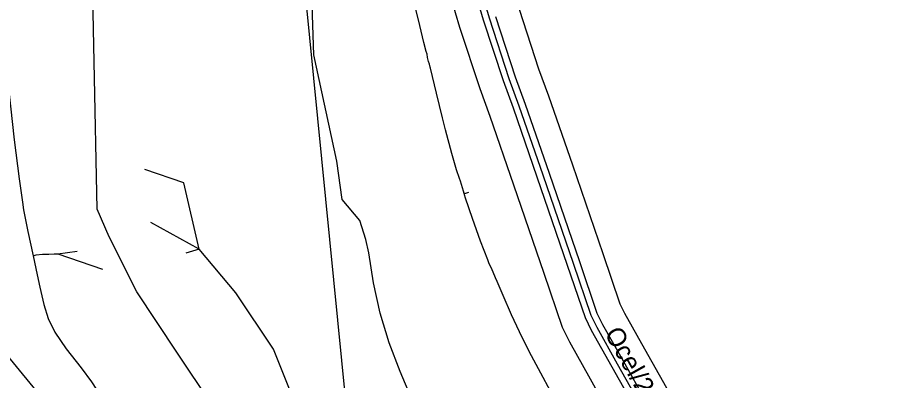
# Model space of a CAD drawing. Extents: x -555222 to -543220, y -1067119 to -1030889.
# Drawn here: x -550360 to -549789, y -1045094 to -1044860 of the extents above; entities that cross this region are included whole.
import ezdxf

# ---------------------------------------------------------------- set-up
doc = ezdxf.new("R2010")
doc.units = 0
for name, color, linetype in [('07_ELEKTRO', 7, 'Continuous'), ('07_KANALIZACE', 7, 'Continuous'), ('07_OCH_P A POPISY TI', 7, 'Continuous'), ('07_PLYNOVOD', 7, 'Continuous'), ('07_SDĚLOVACÍ', 7, 'Continuous')]:
    doc.layers.add(name, color=color, linetype=linetype)

msp = doc.modelspace()

# ---------------------------------------------------------------- linework, layer by layer
at = {"layer": '07_ELEKTRO'}
msp.add_lwpolyline([(-550336.58, -1045114.42), (-550410.66, -1045024.35)], dxfattribs=at)
at = {"layer": '07_KANALIZACE'}
msp.add_lwpolyline([(-550217.13, -1045615.96), (-550259.48, -1045440.34), (-550269.12, -1045408.84), (-550268.16, -1045382.39), (-550263.88, -1045356.4), (-550243.71, -1045306.39), (-550215.78, -1045262), (-550208.66, -1045250.35), (-550203.47, -1045219.62), (-550203.61, -1045193.66), (-550209.22, -1045194.15), (-550212.59, -1045170.19), (-550222.38, -1045132.23), (-550235.02, -1045109.36), (-550257.48, -1045075.54), (-550283.41, -1045036.53), (-550301.24, -1045001.03), (-550308.85, -1044983.14), (-550310.82, -1044888), (-550311.74, -1044845.44)], dxfattribs=at)
at = {"layer": '07_OCH_P A POPISY TI'}
for p, q in [((-550074.86, -1044865.84), (-550080.39, -1044846.82)), ((-550059.57, -1044861.13), (-550064.96, -1044842.6)), ((-550036.64, -1044854.06), (-550024.07, -1044892.57)), ((-550046.76, -1044900.38), (-550059.57, -1044861.13)), ((-550051.93, -1044858.77), (-550039.2, -1044897.78)), ((-550061.89, -1044905.59), (-550074.86, -1044865.84)), ((-550024.07, -1044892.57), (-550017.72, -1044910.07)), ((-550039.2, -1044897.78), (-550032.8, -1044915.42)), ((-550040.34, -1044918.1), (-550046.76, -1044900.38)), ((-550055.42, -1044923.45), (-550061.89, -1044905.59)), ((-550032.8, -1044915.42), (-550017.37, -1044959.88)), ((-550017.72, -1044910.07), (-550002.24, -1044954.66)), ((-550024.93, -1044962.5), (-550040.34, -1044918.1)), ((-550040.06, -1044967.72), (-550055.42, -1044923.45)), ((-550002.24, -1044954.66), (-549982.64, -1045011.78)), ((-550017.37, -1044959.88), (-549997.78, -1045016.95)), ((-550005.36, -1045019.53), (-550024.93, -1044962.5)), ((-550020.5, -1045024.7), (-550040.06, -1044967.72)), ((-549982.64, -1045011.78), (-549971.64, -1045044.22)), ((-549997.78, -1045016.95), (-549986.45, -1045050.37)), ((-549993.85, -1045053.45), (-550005.36, -1045019.53)), ((-550008.66, -1045059.6), (-550020.5, -1045024.7)), ((-549971.64, -1045044.22), (-549968.64, -1045050.28)), ((-549986.45, -1045050.37), (-549982.79, -1045057.75)), ((-549968.64, -1045050.28), (-549955.68, -1045073.36)), ((-549989.87, -1045061.49), (-549993.85, -1045053.45)), ((-549982.79, -1045057.75), (-549969.62, -1045081.2)), ((-550004.02, -1045068.96), (-550008.66, -1045059.6)), ((-549976.6, -1045085.12), (-549989.87, -1045061.49)), ((-549990.54, -1045092.96), (-550004.02, -1045068.96)), ((-549955.68, -1045073.36), (-549930.6, -1045117.93)), ((-549951.53, -1045129.69), (-549976.6, -1045085.12)), ((-549969.62, -1045081.2), (-549944.55, -1045125.77)), ((-549965.48, -1045137.53), (-549990.54, -1045092.96))]:
    msp.add_line(p, q, dxfattribs=at)
at = {"layer": '07_PLYNOVOD'}
msp.add_lwpolyline([(-549948.04, -1045127.73), (-549973.11, -1045083.16), (-549986.33, -1045059.62), (-549990.15, -1045051.91), (-550001.57, -1045018.24), (-550021.15, -1044961.19), (-550036.57, -1044916.76), (-550042.98, -1044899.08), (-550055.75, -1044859.95), (-550061.1, -1044841.54)], dxfattribs=at)
at = {"layer": '07_SDĚLOVACÍ'}
for p, q in [((-550531.78, -1041228.78), (-549789.42, -1048745)), ((-550071.62, -1044973.06), (-550069.17, -1044972.32)), ((-550071.62, -1044973.06), (-550072.12, -1044973.19))]:
    msp.add_line(p, q, dxfattribs=at)
for points in [[(-550154.34, -1044952.18), (-550169.2, -1044883.57), (-550170.5, -1044844.96), (-550189.22, -1044749.95), (-550211.59, -1044742.43)], [(-550016.38, -1045100.77), (-550022.71, -1045089.14), (-550030.23, -1045075.04), (-550036.34, -1045062.33), (-550041.64, -1045051.39), (-550046.94, -1045038.95), (-550050.9, -1045029.94), (-550051.97, -1045027.5), (-550054.46, -1045021.2), (-550056, -1045018.42), (-550056.79, -1045015.86), (-550061.61, -1045003.76), (-550066.71, -1044989.32), (-550071.35, -1044976.16), (-550071.9, -1044974.05), (-550072.12, -1044973.19), (-550072.56, -1044971.48), (-550074.41, -1044965.1), (-550075.03, -1044963.4), (-550077.1, -1044957.73), (-550080.02, -1044947.28), (-550084.14, -1044932.01), (-550086.16, -1044924.27), (-550090.03, -1044908.42), (-550093.88, -1044892.15), (-550094.03, -1044891.52), (-550094.48, -1044889.59), (-550095.06, -1044887.93), (-550095.77, -1044885.26), (-550096.08, -1044883.23), (-550096.6, -1044881.34), (-550098.15, -1044875.65), (-550100.76, -1044864.71), (-550104.41, -1044849.72)], [(-550375.31, -1044856.96), (-550373.27, -1044863.69), (-550369.65, -1044879.82), (-550366.89, -1044897.45), (-550364.79, -1044916.63), (-550362.4, -1044938.38), (-550359.28, -1044963.53), (-550357.01, -1044978.64), (-550356.34, -1044983.72), (-550353.69, -1044997.68), (-550350.27, -1045013.39)], [(-550109.95, -1045197.3), (-550106.98, -1045177.55), (-550105, -1045164.2), (-550099.59, -1045134.09), (-550098.45, -1045127.79), (-550100, -1045120.54), (-550106.57, -1045104.33), (-550113.44, -1045087.9), (-550120.6, -1045069.38), (-550126.22, -1045050.24), (-550130.5, -1045030.86), (-550133.58, -1045011.46), (-550135.46, -1045002.79), (-550139.48, -1044990.44), (-550150.81, -1044976.98), (-550154.34, -1044952.18)], [(-550243.02, -1045008.93), (-550253.01, -1044966.29), (-550278.24, -1044957.53)], [(-550243.02, -1045008.93), (-550274.2, -1044991.8)], [(-550350.27, -1045013.39), (-550348.15, -1045012.78), (-550344.19, -1045012.27), (-550340.13, -1045012.22), (-550336.58, -1045012.04), (-550334.22, -1045012.07)], [(-550334.22, -1045012.07), (-550321.86, -1045010.4)], [(-550334.22, -1045012.07), (-550305.39, -1045021.98)], [(-550243.02, -1045008.93), (-550251.69, -1045011.6)], [(-550149.41, -1045208.76), (-550161.8, -1045167.41), (-550177.96, -1045116.7), (-550195.17, -1045073.67), (-550219.4, -1045037.24), (-550243.02, -1045008.93)], [(-550350.27, -1045013.39), (-550347.57, -1045025.66), (-550345.88, -1045033.5)], [(-550345.88, -1045033.5), (-550343.36, -1045044.82), (-550340.6, -1045053.76), (-550336.2, -1045062.5), (-550328.91, -1045073.28), (-550319.25, -1045085.71), (-550312.49, -1045094.71), (-550305.75, -1045105.25), (-550300.54, -1045114.82), (-550295.79, -1045124.06), (-550291.17, -1045134.56), (-550289.16, -1045143.75), (-550288.25, -1045147.11), (-550286.96, -1045149.84), (-550285.19, -1045151.83), (-550283.09, -1045152.59), (-550278.28, -1045153.09), (-550274.27, -1045153.55), (-550271.11, -1045154.1)]]:
    msp.add_lwpolyline(points, dxfattribs=at)

# ---------------------------------------------------------------- texts
at = {"layer": '07_OCH_P A POPISY TI'}
msp.add_text('Ocel/200', height=12, rotation=299.3075, dxfattribs=at).set_placement((-549981.84, -1045063.39))

doc.saveas('drawing.dxf')
